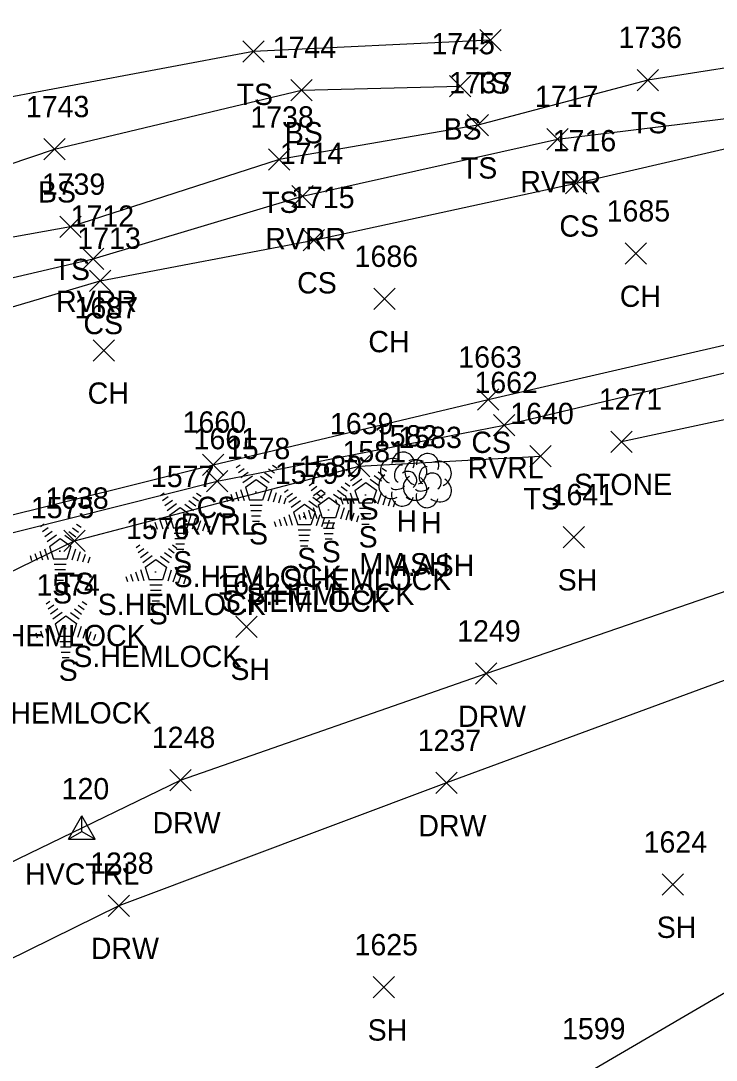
# Model space of a CAD drawing. Extents: x 1621633 to 1624015, y 417863 to 420979.
# Drawn here: x 1621826 to 1621891.2, y 417953.8 to 418051.2 of the extents above; entities that cross this region are included whole.
import ezdxf

# ---------------------------------------------------------------- set-up
doc = ezdxf.new("R2010")
doc.units = 0
for name, color, linetype in [('C_A', 7, 'Continuous'), ('C_I', 7, 'Continuous'), ('CPSM', 7, 'Continuous'), ('L_A', 7, 'Continuous'), ('L_C', 7, 'Continuous'), ('L_I', 7, 'Continuous'), ('L_TIC', 7, 'Continuous'), ('LASF', 7, 'Continuous'), ('LAWA', 7, 'Continuous'), ('LAWE', 7, 'Continuous'), ('LELB', 7, 'Continuous'), ('LTC', 7, 'Continuous'), ('LTD', 7, 'Continuous'), ('R_A', 7, 'Continuous'), ('R_I', 7, 'Continuous'), ('R_TIC', 7, 'Continuous'), ('RDW', 7, 'Continuous')]:
    doc.layers.add(name, color=color, linetype=linetype)

msp = doc.modelspace()

# ---------------------------------------------------------------- linework, layer by layer
at = {"layer": 'CPSM'}
for p, q in [((1621830.505, 417974.49), (1621831.755, 417976.655)), ((1621833.005, 417974.49), (1621831.755, 417976.655)), ((1621831.756, 417975.211), (1621831.755, 417976.655)), ((1621830.505, 417974.49), (1621831.756, 417975.211)), ((1621831.756, 417975.211), (1621831.756, 417975.211)), ((1621831.756, 417975.211), (1621833.005, 417974.49)), ((1621830.505, 417974.49), (1621833.005, 417974.49))]:
    msp.add_line(p, q, dxfattribs=at)
at = {"layer": 'L_TIC'}
for points in [[(1621869.082, 418048.389), (1621871.082, 418050.389)], [(1621871.082, 418048.389), (1621869.082, 418050.389)], [(1621846.864, 418047.319), (1621848.864, 418049.319)], [(1621848.864, 418047.319), (1621846.864, 418049.319)], [(1621883.836, 418044.66), (1621885.836, 418046.66)], [(1621885.836, 418044.66), (1621883.836, 418046.66)], [(1621851.352, 418043.721), (1621853.352, 418045.721)], [(1621853.352, 418043.721), (1621851.352, 418045.721)], [(1621866.236, 418044.074), (1621868.236, 418046.074)], [(1621868.236, 418044.074), (1621866.236, 418046.074)], [(1621867.891, 418040.418), (1621869.891, 418042.418)], [(1621869.891, 418040.418), (1621867.891, 418042.418)], [(1621875.37, 418039.125), (1621877.37, 418041.125)], [(1621877.37, 418039.125), (1621875.37, 418041.125)], [(1621828.213, 418038.175), (1621830.213, 418040.175)], [(1621830.213, 418038.175), (1621828.213, 418040.175)], [(1621849.259, 418037.198), (1621851.259, 418039.198)], [(1621851.259, 418037.198), (1621849.259, 418039.198)], [(1621877.098, 418034.973), (1621879.098, 418036.973)], [(1621879.098, 418034.973), (1621877.098, 418036.973)], [(1621851.452, 418033.783), (1621853.452, 418035.783)], [(1621853.452, 418033.783), (1621851.452, 418035.783)], [(1621829.712, 418030.899), (1621831.712, 418032.899)], [(1621831.712, 418030.899), (1621829.712, 418032.899)], [(1621852.516, 418029.646), (1621854.516, 418031.646)], [(1621854.516, 418029.646), (1621852.516, 418031.646)], [(1621831.841, 418027.899), (1621833.841, 418029.899)], [(1621833.841, 418027.899), (1621831.841, 418029.899)], [(1621882.713, 418028.389), (1621884.713, 418030.389)], [(1621884.713, 418028.389), (1621882.713, 418030.389)], [(1621832.473, 418025.83), (1621834.473, 418027.83)], [(1621834.473, 418025.83), (1621832.473, 418027.83)], [(1621859.139, 418024.135), (1621861.139, 418026.135)], [(1621861.139, 418024.135), (1621859.139, 418026.135)], [(1621832.824, 418019.303), (1621834.824, 418021.303)], [(1621834.824, 418019.303), (1621832.824, 418021.303)], [(1621868.849, 418014.692), (1621870.849, 418016.692)], [(1621870.849, 418014.692), (1621868.849, 418016.692)], [(1621870.363, 418012.308), (1621872.363, 418014.308)], [(1621872.363, 418012.308), (1621870.363, 418014.308)], [(1621881.357, 418010.741), (1621883.357, 418012.741)], [(1621883.357, 418010.741), (1621881.357, 418012.741)], [(1621873.764, 418009.395), (1621875.764, 418011.395)], [(1621875.764, 418009.395), (1621873.764, 418011.395)], [(1621843.088, 418008.589), (1621845.088, 418010.589)], [(1621845.088, 418008.589), (1621843.088, 418010.589)], [(1621856.774, 418008.445), (1621858.774, 418010.445)], [(1621858.774, 418008.445), (1621856.774, 418010.445)], [(1621843.467, 418007.037), (1621845.467, 418009.037)], [(1621845.467, 418007.037), (1621843.467, 418009.037)], [(1621830.079, 418001.462), (1621832.079, 418003.462)], [(1621832.079, 418001.462), (1621830.079, 418003.462)], [(1621876.891, 418001.792), (1621878.891, 418003.792)], [(1621878.891, 418001.792), (1621876.891, 418003.792)], [(1621846.214, 417993.401), (1621848.214, 417995.401)], [(1621848.214, 417993.401), (1621846.214, 417995.401)], [(1621886.177, 417969.218), (1621888.177, 417971.218)], [(1621888.177, 417969.218), (1621886.177, 417971.218)], [(1621859.074, 417959.588), (1621861.074, 417961.588)], [(1621861.074, 417959.588), (1621859.074, 417961.588)]]:
    msp.add_lwpolyline(points, dxfattribs=at)
at = {"layer": 'LASF'}
msp.add_lwpolyline([(1622002.675, 418093.219), (1621997.296, 418076.86), (1621980.179, 418056.204), (1621954.756, 418039.139), (1621928.826, 418024.949), (1621900.016, 418015.523), (1621882.357, 418011.741)], dxfattribs=at)
at = {"layer": 'LAWA'}
msp.add_lwpolyline([(1622001.004, 418030.107), (1621986.32, 418023.658), (1621975.506, 418000.432), (1621955.157, 417983.756), (1621932.198, 417971.155), (1621904.748, 417967.466), (1621879.49, 417952.716), (1621860.189, 417941.587), (1621844.309, 417921.469), (1621821.118, 417913.626), (1621798.12, 417906.333), (1621768.531, 417901.526), (1621742.571, 417889.758), (1621727.863, 417881.174)], dxfattribs=at)
at = {"layer": 'LAWE'}
for points in [[(1621694.469, 417944.857), (1621713.846, 417956.733), (1621742.172, 417966.049), (1621760.532, 417975.456), (1621777.237, 417983.398), (1621792.696, 417991.301), (1621817.095, 418001.163), (1621844.467, 418008.037), (1621871.363, 418013.308), (1621897.422, 418019.495), (1621922.912, 418028.804), (1621945.859, 418038.978), (1621969.359, 418051.535), (1621990.012, 418069.674), (1621996.064, 418084.217), (1621996.533, 418092.287)], [(1621682.822, 417967.998), (1621698.064, 417979.126), (1621716.448, 417990.621), (1621740.687, 418004.296), (1621760.276, 418012.676), (1621779.786, 418018.1), (1621807.782, 418023.044), (1621832.841, 418028.899), (1621852.452, 418034.783), (1621876.37, 418040.125), (1621904.646, 418043.594), (1621931.259, 418052.925), (1621950.617, 418064.927), (1621964.804, 418074.349), (1621971.864, 418081.724)]]:
    msp.add_lwpolyline(points, dxfattribs=at)
at = {"layer": 'LELB'}
for points in [[(1621694.018, 417945.604), (1621713.058, 417958.392), (1621741.418, 417968.002), (1621759.92, 417977.729), (1621776.332, 417984.988), (1621792.046, 417992.579), (1621816.284, 418002.68), (1621844.088, 418009.589), (1621869.849, 418015.692), (1621896.837, 418021.913), (1621921.805, 418030.632), (1621944.897, 418041.057), (1621968.773, 418053.066), (1621989.111, 418070.538), (1621994.262, 418084.512), (1621994.522, 418092.07)], [(1621714.218, 417979.319), (1621742.211, 418002.577), (1621762.579, 418009.214), (1621780.28, 418013.608), (1621808.258, 418019.376), (1621833.473, 418026.83), (1621853.516, 418030.646), (1621878.098, 418035.973), (1621904.446, 418042.094), (1621933.372, 418049.997), (1621951.553, 418063.416), (1621967.003, 418072.955), (1621972.682, 418081.713), (1621977.304, 418089.793)], [(1621962.893, 418084.645), (1621941.499, 418069.284), (1621934.526, 418059.292), (1621911.153, 418049.766), (1621884.836, 418045.66), (1621868.891, 418041.418), (1621850.259, 418038.198), (1621830.712, 418031.899), (1621803.346, 418026.98), (1621784.312, 418024.309)], [(1621870.082, 418049.389), (1621847.864, 418048.319), (1621821.87, 418043.443), (1621810.848, 418041.046), (1621801.708, 418037.161), (1621779.745, 418029.631), (1621758.68, 418020.378), (1621745.692, 418010.927), (1621727.629, 418000.827), (1621708.748, 417989.428), (1621682.341, 417970.694)], [(1621800.802, 418029.566), (1621829.213, 418039.175), (1621852.352, 418044.721), (1621867.236, 418045.074)], [(1621696.619, 417939.068), (1621723.715, 417952.351), (1621743.664, 417962.858), (1621762.067, 417972.573), (1621786.253, 417983.66), (1621806.904, 417990.669), (1621831.079, 418002.462), (1621857.774, 418009.445), (1621874.764, 418010.395)]]:
    msp.add_lwpolyline(points, dxfattribs=at)
at = {"layer": 'LTC'}
for p, q in [((1621846.248, 418009.321), (1621846.603, 418009.578)), ((1621846.458, 418008.856), (1621846.987, 418009.24)), ((1621849.646, 418009.561), (1621850.066, 418009.257)), ((1621856.523, 418009.035), (1621856.878, 418009.293)), ((1621859.922, 418009.276), (1621860.341, 418008.971)), ((1621846.667, 418008.39), (1621847.371, 418008.901)), ((1621846.877, 418007.924), (1621847.755, 418008.562)), ((1621848.533, 418008.516), (1621849.343, 418007.928)), ((1621848.904, 418008.865), (1621849.584, 418008.371)), ((1621849.275, 418009.213), (1621849.825, 418008.814)), ((1621856.733, 418008.57), (1621857.262, 418008.954)), ((1621856.943, 418008.104), (1621857.646, 418008.615)), ((1621857.152, 418007.638), (1621858.03, 418008.276)), ((1621859.18, 418008.579), (1621859.859, 418008.085)), ((1621859.55, 418008.928), (1621860.1, 418008.528)), ((1621847.101, 418007.469), (1621848.113, 418008.203)), ((1621847.101, 418007.469), (1621847.489, 418006.276)), ((1621848.113, 418008.203), (1621849.11, 418007.478)), ((1621849.11, 418007.478), (1621848.719, 418006.276)), ((1621853.067, 418007.648), (1621853.422, 418007.905)), ((1621853.277, 418007.183), (1621853.806, 418007.567)), ((1621856.094, 418007.54), (1621856.644, 418007.141)), ((1621856.465, 418007.888), (1621856.885, 418007.584)), ((1621857.377, 418007.183), (1621858.388, 418007.918)), ((1621858.388, 418007.918), (1621859.385, 418007.193)), ((1621858.808, 418008.231), (1621859.618, 418007.642)), ((1621839.135, 418006.696), (1621839.49, 418006.953)), ((1621839.345, 418006.231), (1621839.874, 418006.615)), ((1621842.162, 418006.588), (1621842.712, 418006.189)), ((1621842.533, 418006.936), (1621842.952, 418006.632)), ((1621845.281, 418006.6), (1621845.433, 418006.132)), ((1621845.736, 418006.817), (1621845.948, 418006.165)), ((1621846.191, 418007.033), (1621846.463, 418006.198)), ((1621846.647, 418007.25), (1621846.978, 418006.231)), ((1621849.548, 418007.208), (1621849.21, 418006.168)), ((1621849.992, 418006.957), (1621849.705, 418006.073)), ((1621850.437, 418006.707), (1621850.2, 418005.978)), ((1621850.881, 418006.457), (1621850.694, 418005.883)), ((1621850.766, 418007), (1621851.121, 418007.257)), ((1621850.976, 418006.534), (1621851.505, 418006.919)), ((1621851.186, 418006.069), (1621851.889, 418006.58)), ((1621853.423, 418006.544), (1621854.102, 418006.05)), ((1621853.486, 418006.717), (1621854.19, 418007.228)), ((1621853.696, 418006.251), (1621854.574, 418006.889)), ((1621853.794, 418006.892), (1621854.343, 418006.493)), ((1621853.92, 418005.796), (1621854.932, 418006.53)), ((1621854.165, 418007.24), (1621854.584, 418006.936)), ((1621854.932, 418006.53), (1621855.929, 418005.805)), ((1621855.352, 418006.843), (1621856.162, 418006.255)), ((1621855.556, 418006.315), (1621855.708, 418005.847)), ((1621855.723, 418007.192), (1621856.402, 418006.698)), ((1621856.011, 418006.531), (1621856.223, 418005.88)), ((1621856.467, 418006.748), (1621856.738, 418005.913)), ((1621856.922, 418006.964), (1621857.253, 418005.945)), ((1621857.377, 418007.183), (1621857.764, 418005.99)), ((1621859.385, 418007.193), (1621858.994, 418005.99)), ((1621859.823, 418006.922), (1621859.485, 418005.883)), ((1621860.268, 418006.672), (1621859.98, 418005.787)), ((1621860.712, 418006.422), (1621860.475, 418005.692)), ((1621839.554, 418005.765), (1621840.258, 418006.276)), ((1621839.764, 418005.299), (1621840.642, 418005.937)), ((1621839.988, 418004.844), (1621841, 418005.578)), ((1621841, 418005.578), (1621841.997, 418004.853)), ((1621841.42, 418005.891), (1621842.23, 418005.303)), ((1621841.791, 418006.24), (1621842.47, 418005.746)), ((1621848.719, 418006.276), (1621847.489, 418006.276)), ((1621848.681, 418005.776), (1621847.536, 418005.776)), ((1621851.395, 418005.603), (1621852.274, 418006.241)), ((1621851.62, 418005.148), (1621852.631, 418005.882)), ((1621852.631, 418005.882), (1621853.629, 418005.157)), ((1621853.01, 418005.36), (1621853.282, 418004.525)), ((1621853.051, 418006.195), (1621853.861, 418005.606)), ((1621853.466, 418005.577), (1621853.797, 418004.558)), ((1621853.92, 418005.796), (1621854.307, 418004.603)), ((1621855.929, 418005.805), (1621855.538, 418004.603)), ((1621856.367, 418005.535), (1621856.029, 418004.495)), ((1621858.994, 418005.99), (1621857.764, 418005.99)), ((1621858.956, 418005.49), (1621857.811, 418005.49)), ((1621861.156, 418006.171), (1621860.97, 418005.597)), ((1621839.078, 418004.408), (1621839.35, 418003.573)), ((1621839.534, 418004.625), (1621839.865, 418003.606)), ((1621839.988, 418004.844), (1621840.375, 418003.651)), ((1621841.997, 418004.853), (1621841.606, 418003.651)), ((1621842.435, 418004.583), (1621842.097, 418003.543)), ((1621848.597, 418005.276), (1621847.609, 418005.276)), ((1621848.513, 418004.776), (1621847.681, 418004.776)), ((1621850.254, 418004.496), (1621850.466, 418003.844)), ((1621850.71, 418004.712), (1621850.981, 418003.877)), ((1621851.165, 418004.929), (1621851.496, 418003.909)), ((1621851.62, 418005.148), (1621852.007, 418003.954)), ((1621852.1, 418004.927), (1621852.252, 418004.459)), ((1621852.555, 418005.144), (1621852.767, 418004.492)), ((1621853.629, 418005.157), (1621853.237, 418003.954)), ((1621854.066, 418004.886), (1621853.728, 418003.847)), ((1621854.511, 418004.636), (1621854.223, 418003.751)), ((1621855.538, 418004.603), (1621854.307, 418004.603)), ((1621854.955, 418004.386), (1621854.718, 418003.656)), ((1621856.811, 418005.284), (1621856.524, 418004.4)), ((1621857.256, 418005.034), (1621857.019, 418004.305)), ((1621857.7, 418004.784), (1621857.513, 418004.21)), ((1621858.872, 418004.99), (1621857.884, 418004.99)), ((1621858.788, 418004.49), (1621857.957, 418004.49)), ((1621827.877, 418003.783), (1621828.232, 418004.04)), ((1621828.087, 418003.317), (1621828.616, 418003.701)), ((1621830.904, 418003.675), (1621831.454, 418003.276)), ((1621831.275, 418004.023), (1621831.694, 418003.719)), ((1621838.167, 418003.975), (1621838.32, 418003.507)), ((1621838.623, 418004.192), (1621838.835, 418003.54)), ((1621841.606, 418003.651), (1621840.375, 418003.651)), ((1621842.879, 418004.332), (1621842.592, 418003.448)), ((1621843.324, 418004.082), (1621843.087, 418003.353)), ((1621843.768, 418003.832), (1621843.581, 418003.258)), ((1621848.429, 418004.276), (1621847.754, 418004.276)), ((1621849.799, 418004.279), (1621849.951, 418003.811)), ((1621853.237, 418003.954), (1621852.007, 418003.954)), ((1621853.199, 418003.454), (1621852.054, 418003.454)), ((1621855.5, 418004.103), (1621854.355, 418004.103)), ((1621855.416, 418003.603), (1621854.427, 418003.603)), ((1621855.399, 418004.136), (1621855.213, 418003.561)), ((1621858.705, 418003.99), (1621858.03, 418003.99)), ((1621828.296, 418002.851), (1621829, 418003.363)), ((1621828.506, 418002.386), (1621829.384, 418003.024)), ((1621828.73, 418001.931), (1621829.742, 418002.665)), ((1621829.742, 418002.665), (1621830.739, 418001.94)), ((1621830.162, 418002.978), (1621830.972, 418002.389)), ((1621830.533, 418003.326), (1621831.212, 418002.833)), ((1621841.567, 418003.151), (1621840.423, 418003.151)), ((1621841.484, 418002.651), (1621840.495, 418002.651)), ((1621853.115, 418002.954), (1621852.127, 418002.954)), ((1621853.031, 418002.454), (1621852.2, 418002.454)), ((1621855.332, 418003.103), (1621854.5, 418003.103)), ((1621855.248, 418002.603), (1621854.573, 418002.603)), ((1621827.82, 418001.495), (1621828.092, 418000.66)), ((1621828.276, 418001.711), (1621828.607, 418000.692)), ((1621828.73, 418001.931), (1621829.117, 418000.737)), ((1621830.739, 418001.94), (1621830.348, 418000.737)), ((1621831.177, 418001.669), (1621830.839, 418000.63)), ((1621836.853, 418001.826), (1621837.208, 418002.084)), ((1621837.063, 418001.361), (1621837.592, 418001.745)), ((1621839.88, 418001.718), (1621840.43, 418001.319)), ((1621840.252, 418002.067), (1621840.671, 418001.762)), ((1621841.4, 418002.151), (1621840.568, 418002.151)), ((1621841.316, 418001.651), (1621840.641, 418001.651)), ((1621852.948, 418001.954), (1621852.273, 418001.954)), ((1621826.91, 418001.062), (1621827.062, 418000.594)), ((1621827.365, 418001.279), (1621827.577, 418000.627)), ((1621830.348, 418000.737), (1621829.117, 418000.737)), ((1621831.621, 418001.419), (1621831.334, 418000.534)), ((1621832.066, 418001.169), (1621831.829, 418000.439)), ((1621832.51, 418000.919), (1621832.323, 418000.344)), ((1621837.272, 418000.895), (1621837.976, 418001.406)), ((1621837.482, 418000.429), (1621838.36, 418001.067)), ((1621837.707, 417999.974), (1621838.718, 418000.709)), ((1621838.718, 418000.709), (1621839.715, 417999.984)), ((1621839.138, 418001.022), (1621839.948, 418000.433)), ((1621839.51, 418001.37), (1621840.189, 418000.876)), ((1621830.309, 418000.237), (1621829.165, 418000.237)), ((1621830.226, 417999.737), (1621829.237, 417999.737)), ((1621836.797, 417999.539), (1621837.068, 417998.703)), ((1621837.252, 417999.755), (1621837.583, 417998.736)), ((1621837.707, 417999.974), (1621838.094, 417998.781)), ((1621839.715, 417999.984), (1621839.324, 417998.781)), ((1621840.153, 417999.713), (1621839.815, 417998.673)), ((1621830.142, 417999.237), (1621829.31, 417999.237)), ((1621830.058, 417998.737), (1621829.383, 417998.737)), ((1621835.886, 417999.106), (1621836.038, 417998.638)), ((1621836.341, 417999.322), (1621836.553, 417998.671)), ((1621839.324, 417998.781), (1621838.094, 417998.781)), ((1621840.597, 417999.463), (1621840.31, 417998.578)), ((1621841.042, 417999.213), (1621840.805, 417998.483)), ((1621841.486, 417998.962), (1621841.3, 417998.388)), ((1621839.286, 417998.281), (1621838.141, 417998.281)), ((1621839.202, 417997.781), (1621838.214, 417997.781)), ((1621828.41, 417996.531), (1621828.764, 417996.789)), ((1621831.808, 417996.772), (1621832.227, 417996.467)), ((1621839.118, 417997.281), (1621838.287, 417997.281)), ((1621839.035, 417996.781), (1621838.36, 417996.781)), ((1621828.619, 417996.066), (1621829.148, 417996.45)), ((1621828.829, 417995.6), (1621829.532, 417996.111)), ((1621829.038, 417995.134), (1621829.917, 417995.772)), ((1621830.695, 417995.727), (1621831.504, 417995.138)), ((1621831.066, 417996.075), (1621831.745, 417995.581)), ((1621831.437, 417996.423), (1621831.986, 417996.024)), ((1621829.263, 417994.679), (1621830.275, 417995.414)), ((1621829.263, 417994.679), (1621829.65, 417993.486)), ((1621830.275, 417995.414), (1621831.272, 417994.689)), ((1621831.272, 417994.689), (1621830.88, 417993.486)), ((1621827.442, 417993.811), (1621827.594, 417993.343)), ((1621827.897, 417994.027), (1621828.109, 417993.376)), ((1621828.353, 417994.244), (1621828.624, 417993.408)), ((1621828.808, 417994.46), (1621829.139, 417993.441)), ((1621831.709, 417994.418), (1621831.371, 417993.378)), ((1621832.154, 417994.168), (1621831.866, 417993.283)), ((1621832.598, 417993.918), (1621832.361, 417993.188)), ((1621833.042, 417993.667), (1621832.856, 417993.093)), ((1621830.88, 417993.486), (1621829.65, 417993.486)), ((1621830.842, 417992.986), (1621829.697, 417992.986)), ((1621830.758, 417992.486), (1621829.77, 417992.486)), ((1621830.675, 417991.986), (1621829.843, 417991.986)), ((1621830.591, 417991.486), (1621829.916, 417991.486))]:
    msp.add_line(p, q, dxfattribs=at)
at = {"layer": 'LTD'}
for p, q in [((1621861.839, 418008.298), (1621861.839, 418008.298)), ((1621861.839, 418008.298), (1621861.839, 418008.298)), ((1621864.141, 418008.149), (1621864.141, 418008.149)), ((1621864.141, 418008.149), (1621864.141, 418008.149))]:
    msp.add_line(p, q, dxfattribs=at)
for centre in [(1621861.885, 418009.732), (1621864.188, 418009.583)]:
    msp.add_arc(centre, 1.047, 335.52715, 180.95627, dxfattribs=at)
for centre, major_axis, ratio, start_param, end_param in [((1621861.047, 418008.965), (1.21, -0.512), 0.895232, 1.570796, 4.712389), ((1621862.88, 418008.882), (-1.141, -0.483), 0.949671, 1.570796, 4.712389), ((1621861.63, 418008.756), (-0.208, -0.792), 0.645439, 3.141593, 6.283185), ((1621863.349, 418008.815), (1.21, -0.512), 0.895232, 1.570796, 4.712389), ((1621863.932, 418008.607), (-0.208, -0.792), 0.645439, 3.141593, 6.283185), ((1621865.182, 418008.732), (-1.141, -0.483), 0.949671, 1.570796, 4.712389), ((1621860.755, 418007.59), (0.584, -1.042), 0.959034, 3.141593, 6.283185), ((1621863.058, 418007.44), (0.584, -1.042), 0.959034, 3.141593, 6.283185), ((1621862.339, 418008.131), (-0.5, 0.667), 0.989748, 3.141593, 6.283185), ((1621862.839, 418007.465), (-1.09, 0.792), 0.841452, 1.570796, 4.712389), ((1621864.641, 418007.982), (-0.5, 0.667), 0.989748, 3.141593, 6.283185), ((1621861.381, 418007.548), (-0.625, -0.083), 0.423636, 0, 3.141593), ((1621863.683, 418007.399), (-0.625, -0.083), 0.423636, 0, 3.141593), ((1621865.141, 418007.315), (-1.09, 0.792), 0.841452, 1.570796, 4.712389), ((1621861.839, 418006.798), (0.265, 1.061), 0.942809, 1.570796, 4.712389), ((1621864.141, 418006.649), (0.265, 1.061), 0.942809, 1.570796, 4.712389)]:
    msp.add_ellipse(centre, major_axis=major_axis, ratio=ratio, start_param=start_param, end_param=end_param, dxfattribs=at)
at = {"layer": 'R_TIC'}
for points in [[(1621868.66, 417989.005), (1621870.66, 417991.005)], [(1621870.66, 417989.005), (1621868.66, 417991.005)], [(1621840.022, 417979.019), (1621842.022, 417981.019)], [(1621842.022, 417979.019), (1621840.022, 417981.019)], [(1621864.95, 417978.751), (1621866.95, 417980.751)], [(1621866.95, 417978.751), (1621864.95, 417980.751)], [(1621834.24, 417967.23), (1621836.24, 417969.23)], [(1621836.24, 417967.23), (1621834.24, 417969.23)]]:
    msp.add_lwpolyline(points, dxfattribs=at)
at = {"layer": 'RDW'}
msp.add_lwpolyline([(1621894.363, 417990.232), (1621865.95, 417979.751), (1621835.24, 417968.23), (1621807.862, 417954.759), (1621779.016, 417937.89), (1621749.255, 417923.342), (1621721.772, 417904.02), (1621715.875, 417914.033), (1621734.513, 417925.445), (1621760.095, 417937.756), (1621788.575, 417952.475), (1621814.671, 417967.246), (1621841.022, 417980.019), (1621869.66, 417990.005), (1621898.189, 417999.842)], dxfattribs=at)

# ---------------------------------------------------------------- texts
at = {"layer": 'C_A'}
msp.add_text('HVCTRL', height=2, dxfattribs=at).set_placement((1621826.448, 417970.211))
at = {"layer": 'C_I'}
msp.add_text('120', height=2, dxfattribs=at).set_placement((1621829.874, 417978.211))
at = {"layer": 'L_A'}
for s, p in [('TS', (1621868.491, 418044.389)), ('TS', (1621846.274, 418043.319)), ('TS', (1621883.246, 418040.66)), ('BS', (1621850.793, 418039.721)), ('BS', (1621865.677, 418040.074)), ('TS', (1621867.3, 418036.418)), ('RVRR', (1621872.882, 418035.125)), ('BS', (1621827.654, 418034.175)), ('TS', (1621848.669, 418033.198)), ('CS', (1621876.539, 418030.973)), ('RVRR', (1621848.964, 418029.783)), ('TS', (1621829.121, 418026.899)), ('CS', (1621851.957, 418025.646)), ('RVRR', (1621829.353, 418023.899)), ('CH', (1621882.202, 418024.389)), ('CS', (1621831.914, 418021.83)), ('CH', (1621858.627, 418020.135)), ('CH', (1621832.312, 418015.303)), ('CS', (1621868.29, 418010.692)), ('RVRL', (1621867.93, 418008.308)), ('STONE', (1621877.9, 418006.741)), ('TS', (1621873.174, 418005.395)), ('CS', (1621842.529, 418004.589)), ('TS', (1621856.183, 418004.445)), ('RVRL', (1621841.034, 418003.037)), ('H', (1621861.272, 418003.298)), ('H', (1621863.574, 418003.149)), ('S', (1621847.439, 418002.113)), ('S', (1621857.714, 418001.827)), ('S', (1621854.258, 418000.44)), ('S', (1621840.326, 417999.488)), ('S', (1621851.957, 417999.792)), ('TS', (1621829.488, 417997.462)), ('SH', (1621876.38, 417997.792)), ('S', (1621829.068, 417996.575)), ('S', (1621838.044, 417994.618)), ('S', (1621829.6, 417989.323)), ('SH', (1621845.702, 417989.401)), ('SH', (1621885.665, 417965.218)), ('SH', (1621858.562, 417955.588))]:
    msp.add_text(s, height=2, dxfattribs=at).set_placement(p)
at = {"layer": 'L_C'}
for s, p in [('M.ASH', (1621857.791, 417999.298)), ('M.ASH', (1621860.094, 417999.149)), ('S.HEMLOCK', (1621840.368, 417998.113)), ('S.HEMLOCK', (1621850.643, 417997.827)), ('S.HEMLOCK', (1621844.886, 417995.792)), ('S.HEMLOCK', (1621847.187, 417996.44)), ('S.HEMLOCK', (1621833.255, 417995.488)), ('S.HEMLOCK', (1621821.997, 417992.575)), ('S.HEMLOCK', (1621830.973, 417990.618)), ('S.HEMLOCK', (1621822.529, 417985.323))]:
    msp.add_text(s, height=2, dxfattribs=at).set_placement(p)
at = {"layer": 'L_I'}
for s, p in [('1736', (1621882.088, 418048.66)), ('1744', (1621849.659, 418047.721)), ('1745', (1621864.543, 418048.074)), ('1737', (1621866.198, 418044.418)), ('1717', (1621874.244, 418043.125)), ('1743', (1621826.521, 418042.175)), ('1738', (1621847.567, 418041.198)), ('1716', (1621875.917, 418038.973)), ('1714', (1621850.326, 418037.783)), ('1739', (1621828.011, 418034.899)), ('1715', (1621851.39, 418033.646)), ('1712', (1621830.715, 418031.899)), ('1685', (1621880.973, 418032.389)), ('1713', (1621831.347, 418029.83)), ('1686', (1621857.344, 418028.135)), ('1687', (1621831.084, 418023.303)), ('1663', (1621867.062, 418018.692)), ('1662', (1621868.575, 418016.308)), ('1271', (1621880.231, 418014.741)), ('1640', (1621871.937, 418013.395)), ('1660', (1621841.214, 418012.589)), ('1639', (1621855.026, 418012.445)), ('1582', (1621859.146, 418011.298)), ('1583', (1621861.448, 418011.149)), ('1661', (1621842.246, 418011.037)), ('1578', (1621845.36, 418010.113)), ('1581', (1621856.202, 418009.827)), ('1580', (1621852.092, 418008.44)), ('1577', (1621838.247, 418007.488)), ('1579', (1621849.871, 418007.792)), ('1638', (1621828.339, 418005.462)), ('1641', (1621875.718, 418005.792)), ('1575', (1621826.989, 418004.575)), ('1576', (1621835.91, 418002.618)), ('1574', (1621827.521, 417997.323)), ('1642', (1621844.473, 417997.401)), ('1624', (1621884.437, 417973.218)), ('1625', (1621857.334, 417963.588)), ('1599', (1621876.789, 417955.716))]:
    msp.add_text(s, height=2, dxfattribs=at).set_placement(p)
at = {"layer": 'LTC'}
for p in [(1621847.996, 418007.217), (1621858.271, 418006.931), (1621854.815, 418005.544), (1621840.882, 418004.592), (1621852.514, 418004.896), (1621829.624, 418001.679), (1621838.601, 417999.722), (1621830.157, 417994.427)]:
    msp.add_text('.', height=1.037, rotation=270, dxfattribs=at).set_placement(p)
at = {"layer": 'R_A'}
for p in [(1621867.03, 417985.005), (1621838.392, 417975.019), (1621863.32, 417974.751), (1621832.611, 417963.23)]:
    msp.add_text('DRW', height=2, dxfattribs=at).set_placement(p)
at = {"layer": 'R_I'}
for s, p in [('1249', (1621866.959, 417993.005)), ('1248', (1621838.329, 417983.019)), ('1237', (1621863.257, 417982.751)), ('1238', (1621832.548, 417971.23))]:
    msp.add_text(s, height=2, dxfattribs=at).set_placement(p)

doc.saveas('drawing.dxf')
